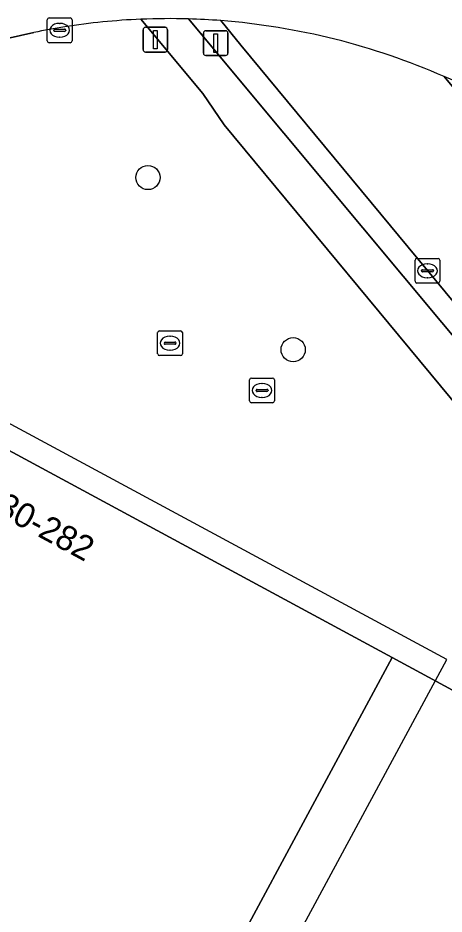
# Model space of a CAD drawing. Extents: x 159489 to 160304, y 383825 to 384531.
# Drawn here: x 159952.57 to 159969.79, y 384218.65 to 384254.88 of the extents above; entities that cross this region are included whole.
import ezdxf

# ---------------------------------------------------------------- set-up
doc = ezdxf.new("R2010")
doc.units = 0
for name, color, linetype in [('IMGEO_Berm_groen', 7, 'Continuous'), ('IMGEO_Boom', 7, 'Continuous'), ('IMGEO_Fietspad_gesloten', 7, 'Continuous'), ('IMGEO_Groenvoorziening', 7, 'Continuous'), ('IMGEO_Kolk', 7, 'Continuous'), ('IMGEO_Lichtmast', 7, 'Continuous'), ('IMGEO_OVBaan_gesloten', 7, 'Continuous'), ('IMGEO_Pand', 7, 'Continuous'), ('IMGEO_Pand_nummerreeks', 7, 'Continuous'), ('IMGEO_Pand_overbouw', 7, 'Continuous'), ('IMGEO_Rijbaan_lokaal_gesloten', 7, 'Continuous'), ('IMGEO_Verkeerseiland_open', 7, 'Continuous'), ('IMGEO_Verkeersregelinstallatiepaal', 7, 'Continuous'), ('IMGEO_Voetpad_open', 7, 'Continuous')]:
    doc.layers.add(name, color=color, linetype=linetype)

msp = doc.modelspace()

# ---------------------------------------------------------------- linework, layer by layer
at = {"layer": 'IMGEO_Berm_groen'}
msp.add_lwpolyline([(159969.786, 384252.506), (160028.141, 384182.05), (160030.552, 384184.07), (159981.084, 384243.71)], dxfattribs=at)
msp.add_arc((159961.544, 384231.122), 22.918, 46.5819, 68.9231, dxfattribs=at)
at = {"layer": 'IMGEO_Boom'}
for centre in [(159957.82, 384248.425), (159963.688, 384241.466)]:
    msp.add_circle(centre, 0.489, dxfattribs=at)
at = {"layer": 'IMGEO_Fietspad_gesloten'}
for points in [[(159957.532, 384254.825), (159960.033, 384251.817), (159960.897, 384250.561), (160029.527, 384167.731), (160030.452, 384166.645), (160032.238, 384164.549)], [(159961.686, 384252.179), (159959.937, 384254.261), (159959.452, 384254.838)], [(160032.453, 384167.34), (159961.686, 384252.179)]]:
    msp.add_lwpolyline(points, dxfattribs=at)
msp.add_arc((159958.681, 384226.911), 27.937, 88.4187, 92.3572, dxfattribs=at)
at = {"layer": 'IMGEO_Groenvoorziening'}
msp.add_lwpolyline([(159982.197, 384221.174), (159967.686, 384229.02), (159951.577, 384199.109), (159928.39, 384211.596), (159927.794, 384210.489), (159967.949, 384188.903), (159982.328, 384181.173), (159984.895, 384182.371), (159986.818, 384178.787), (159991.4, 384176.315), (159993.92, 384177.521), (159995.948, 384173.906), (160023.092, 384159.367), (160025.82, 384157.906), (160029.234, 384164.348)], close=True, dxfattribs=at)
at = {"layer": 'IMGEO_Kolk'}
for p, q in [((159953.753, 384253.951), (159953.753, 384254.803)), ((159953.828, 384254.877), (159954.68, 384254.877)), ((159954.754, 384254.803), (159954.754, 384253.951)), ((159954.055, 384254.42), (159954.453, 384254.42)), ((159954.241, 384254.657), (159954.266, 384254.657)), ((159954.012, 384254.371), (159954.012, 384254.383)), ((159954.45, 384254.334), (159954.052, 384254.334)), ((159954.264, 384254.097), (159954.239, 384254.097)), ((159954.496, 384254.383), (159954.496, 384254.371)), ((159954.68, 384253.877), (159953.828, 384253.877)), ((159968.614, 384244.23), (159968.614, 384245.082)), ((159968.689, 384245.156), (159969.541, 384245.156)), ((159969.615, 384245.082), (159969.615, 384244.23)), ((159968.873, 384244.65), (159968.873, 384244.662)), ((159969.311, 384244.613), (159968.913, 384244.613)), ((159968.916, 384244.699), (159969.314, 384244.699)), ((159969.102, 384244.936), (159969.127, 384244.936)), ((159969.357, 384244.662), (159969.357, 384244.65)), ((159969.125, 384244.376), (159969.1, 384244.376)), ((159969.541, 384244.156), (159968.689, 384244.156)), ((159958.212, 384241.304), (159958.212, 384242.156)), ((159958.287, 384242.23), (159959.139, 384242.23)), ((159959.213, 384242.156), (159959.213, 384241.304)), ((159958.471, 384241.724), (159958.471, 384241.736)), ((159958.514, 384241.773), (159958.912, 384241.773)), ((159958.7, 384242.01), (159958.725, 384242.01)), ((159958.955, 384241.736), (159958.955, 384241.724)), ((159958.909, 384241.687), (159958.511, 384241.687)), ((159958.723, 384241.45), (159958.698, 384241.45)), ((159959.139, 384241.23), (159958.287, 384241.23)), ((159962.004, 384240.319), (159962.856, 384240.319)), ((159961.929, 384239.393), (159961.929, 384240.245)), ((159962.417, 384240.099), (159962.442, 384240.099)), ((159962.93, 384240.245), (159962.93, 384239.393)), ((159962.188, 384239.813), (159962.188, 384239.825)), ((159962.626, 384239.776), (159962.228, 384239.776)), ((159962.231, 384239.862), (159962.629, 384239.862)), ((159962.672, 384239.825), (159962.672, 384239.813)), ((159962.856, 384239.319), (159962.004, 384239.319)), ((159962.44, 384239.539), (159962.415, 384239.539))]:
    msp.add_line(p, q, dxfattribs=at)
for points in [[(159953.753, 384253.951), (159953.753, 384254.803)], [(159953.828, 384254.877), (159954.68, 384254.877)], [(159954.754, 384254.803), (159954.754, 384253.951)], [(159954.68, 384253.877), (159953.828, 384253.877)], [(159968.614, 384244.23), (159968.614, 384245.082)], [(159968.689, 384245.156), (159969.541, 384245.156)], [(159969.615, 384245.082), (159969.615, 384244.23)], [(159969.541, 384244.156), (159968.689, 384244.156)], [(159958.212, 384241.304), (159958.212, 384242.156)], [(159958.287, 384242.23), (159959.139, 384242.23)], [(159959.213, 384242.156), (159959.213, 384241.304)], [(159959.139, 384241.23), (159958.287, 384241.23)], [(159962.004, 384240.319), (159962.856, 384240.319)], [(159961.929, 384239.393), (159961.929, 384240.245)], [(159962.93, 384240.245), (159962.93, 384239.393)], [(159962.856, 384239.319), (159962.004, 384239.319)]]:
    msp.add_lwpolyline(points, dxfattribs=at)
for centre, radius, start, end in [((159953.83, 384254.801), 0.0765, 91.552, 178.448), ((159953.83, 384254.801), 0.0765, 91.552, 178.448), ((159954.678, 384254.801), 0.0765, 1.552, 88.448), ((159954.678, 384254.801), 0.0765, 1.552, 88.448), ((159954.052, 384254.38), 0.0403, 85.8775, 175.7526), ((159954.457, 384254.382), 0.0386, 1.7309, 96.639), ((159954.049, 384254.37), 0.0366, 178.938, 274.7102), ((159954.453, 384254.377), 0.043, 264.8664, 352.4533), ((159953.83, 384253.953), 0.0765, 181.552, 268.448), ((159953.83, 384253.953), 0.0765, 181.552, 268.448), ((159954.678, 384253.953), 0.0765, 271.552, 358.448), ((159954.678, 384253.953), 0.0765, 271.552, 358.448), ((159968.691, 384245.08), 0.0765, 91.552, 178.448), ((159968.691, 384245.08), 0.0765, 91.552, 178.448), ((159969.539, 384245.08), 0.0765, 1.552, 88.448), ((159969.539, 384245.08), 0.0765, 1.552, 88.448), ((159968.913, 384244.659), 0.0403, 85.8775, 175.7526), ((159968.91, 384244.649), 0.0366, 178.938, 274.7102), ((159969.314, 384244.656), 0.043, 264.8664, 352.4533), ((159969.318, 384244.661), 0.0386, 1.7309, 96.639), ((159968.691, 384244.232), 0.0765, 181.552, 268.448), ((159968.691, 384244.232), 0.0765, 181.552, 268.448), ((159969.539, 384244.232), 0.0765, 271.552, 358.448), ((159969.539, 384244.232), 0.0765, 271.552, 358.448), ((159958.289, 384242.154), 0.0765, 91.552, 178.448), ((159958.289, 384242.154), 0.0765, 91.552, 178.448), ((159959.137, 384242.154), 0.0765, 1.552, 88.448), ((159959.137, 384242.154), 0.0765, 1.552, 88.448), ((159958.511, 384241.733), 0.0403, 85.8775, 175.7526), ((159958.508, 384241.723), 0.0366, 178.938, 274.7102), ((159958.912, 384241.73), 0.043, 264.8664, 352.4533), ((159958.916, 384241.735), 0.0386, 1.7309, 96.639), ((159958.289, 384241.306), 0.0765, 181.552, 268.448), ((159958.289, 384241.306), 0.0765, 181.552, 268.448), ((159959.137, 384241.306), 0.0765, 271.552, 358.448), ((159959.137, 384241.306), 0.0765, 271.552, 358.448), ((159962.006, 384240.243), 0.0765, 91.552, 178.448), ((159962.006, 384240.243), 0.0765, 91.552, 178.448), ((159962.854, 384240.243), 0.0765, 1.552, 88.448), ((159962.854, 384240.243), 0.0765, 1.552, 88.448), ((159962.228, 384239.822), 0.0403, 85.8775, 175.7526), ((159962.225, 384239.812), 0.0366, 178.938, 274.7102), ((159962.629, 384239.819), 0.043, 264.8664, 352.4533), ((159962.633, 384239.824), 0.0386, 1.7309, 96.639), ((159962.006, 384239.395), 0.0765, 181.552, 268.448), ((159962.006, 384239.395), 0.0765, 181.552, 268.448), ((159962.854, 384239.395), 0.0765, 271.552, 358.448), ((159962.854, 384239.395), 0.0765, 271.552, 358.448)]:
    msp.add_arc(centre, radius, start, end, dxfattribs=at)
for centre, major_axis, ratio, start_param, end_param in [((159954.24, 384254.377), (-0.387, 0.002), 0.722429, 4.712389, 7.853982), ((159954.265, 384254.377), (-0.39, 0.002), 0.717154, 1.570796, 4.712389), ((159969.101, 384244.656), (-0.387, 0.002), 0.722429, 4.712389, 7.853982), ((159969.126, 384244.656), (-0.39, 0.002), 0.717154, 1.570796, 4.712389), ((159958.699, 384241.73), (-0.387, 0.002), 0.722429, 4.712389, 7.853982), ((159958.724, 384241.73), (-0.39, 0.002), 0.717154, 1.570796, 4.712389), ((159962.416, 384239.819), (-0.387, 0.002), 0.722429, 4.712389, 7.853982), ((159962.441, 384239.819), (-0.39, 0.002), 0.717154, 1.570796, 4.712389)]:
    msp.add_ellipse(centre, major_axis=major_axis, ratio=ratio, start_param=start_param, end_param=end_param, dxfattribs=at)
at = {"layer": 'IMGEO_Lichtmast'}
for p, q in [((159960.063, 384253.458), (159960.063, 384254.258)), ((159960.063, 384254.258), (159960.063, 384253.458)), ((159960.163, 384254.358), (159960.953, 384254.358)), ((159960.953, 384254.358), (159960.163, 384254.358)), ((159961.053, 384254.258), (159961.053, 384253.458)), ((159961.053, 384253.458), (159961.053, 384254.258)), ((159960.953, 384253.358), (159960.163, 384253.358)), ((159960.163, 384253.358), (159960.953, 384253.358))]:
    msp.add_line(p, q, dxfattribs=at)
msp.add_lwpolyline([(159960.483, 384254.233), (159960.633, 384254.233), (159960.633, 384253.483), (159960.483, 384253.483), (159960.483, 384254.233)], dxfattribs=at)
for centre, start, end in [((159960.163, 384254.258), 90, 180), ((159960.163, 384254.258), 90, 180), ((159960.953, 384254.258), 0, 90), ((159960.953, 384254.258), 360, 90), ((159960.163, 384253.458), 180, 270), ((159960.163, 384253.458), 180, 270), ((159960.953, 384253.458), 270, 0), ((159960.953, 384253.458), 270, 0)]:
    msp.add_arc(centre, 0.1, start, end, dxfattribs=at)
at = {"layer": 'IMGEO_OVBaan_gesloten'}
msp.add_lwpolyline([(159951.164, 384253.832), (159953.211, 384254.289)], dxfattribs=at)
for centre, radius, start, end in [((159958.697, 384227.713), 27.137, 92.4615, 98.9856), ((159958.681, 384226.911), 27.937, 88.4187, 92.3572), ((159958.68, 384228.095), 26.754, 85.5364, 88.3462), ((159958.606, 384227.036), 27.816, 66.3012, 85.5546), ((159958.952, 384226.397), 28.477, 99.0769, 101.6297), ((159961.544, 384231.122), 22.918, 46.5819, 68.9231)]:
    msp.add_arc(centre, radius, start, end, dxfattribs=at)
at = {"layer": 'IMGEO_Pand'}
msp.add_lwpolyline([(159967.686, 384229.02), (159944.524, 384241.543), (159928.39, 384211.596), (159951.577, 384199.109)], close=True, dxfattribs=at)
at = {"layer": 'IMGEO_Pand_overbouw'}
msp.add_lwpolyline([(159953.299, 384198.181), (159969.896, 384228.943), (159943.238, 384243.325), (159926.605, 384212.558), (159928.39, 384211.596), (159944.07, 384240.7), (159944.524, 384241.543), (159945.039, 384241.265), (159967.686, 384229.02), (159951.577, 384199.109)], close=True, dxfattribs=at)
at = {"layer": 'IMGEO_Rijbaan_lokaal_gesloten'}
for points in [[(159960.762, 384254.768), (159961.57, 384253.773), (160030.037, 384171.103), (160034.331, 384174.603), (160033.026, 384176.155), (160028.141, 384182.05)], [(160028.141, 384182.05), (159969.786, 384252.506)]]:
    msp.add_lwpolyline(points, dxfattribs=at)
msp.add_arc((159958.606, 384227.036), 27.816, 66.3012, 85.5546, dxfattribs=at)
at = {"layer": 'IMGEO_Verkeerseiland_open'}
for points in [[(159959.452, 384254.838), (159959.937, 384254.261), (159961.686, 384252.179), (160032.453, 384167.34)], [(159961.57, 384253.773), (159960.762, 384254.768)], [(160031.533, 384169.297), (160030.037, 384171.103), (159961.57, 384253.773)]]:
    msp.add_lwpolyline(points, dxfattribs=at)
msp.add_arc((159958.68, 384228.095), 26.754, 85.5364, 88.3462, dxfattribs=at)
at = {"layer": 'IMGEO_Verkeersregelinstallatiepaal'}
for p, q in [((159957.62, 384253.598), (159957.62, 384254.398)), ((159957.62, 384254.398), (159957.62, 384253.598)), ((159957.72, 384254.498), (159958.51, 384254.498)), ((159958.51, 384254.498), (159957.72, 384254.498)), ((159958.61, 384254.398), (159958.61, 384253.598)), ((159958.61, 384253.598), (159958.61, 384254.398)), ((159958.51, 384253.498), (159957.72, 384253.498)), ((159957.72, 384253.498), (159958.51, 384253.498))]:
    msp.add_line(p, q, dxfattribs=at)
msp.add_lwpolyline([(159958.04, 384254.373), (159958.19, 384254.373), (159958.19, 384253.623), (159958.04, 384253.623), (159958.04, 384254.373)], dxfattribs=at)
for centre, start, end in [((159957.72, 384254.398), 90, 180), ((159957.72, 384254.398), 90, 180), ((159958.51, 384254.398), 0, 90), ((159958.51, 384254.398), 360, 90), ((159957.72, 384253.598), 180, 270), ((159957.72, 384253.598), 180, 270), ((159958.51, 384253.598), 270, 0), ((159958.51, 384253.598), 270, 0)]:
    msp.add_arc(centre, 0.1, start, end, dxfattribs=at)
at = {"layer": 'IMGEO_Voetpad_open'}
for points in [[(159960.897, 384250.561), (159960.033, 384251.817), (159957.532, 384254.825)], [(159953.211, 384254.289), (159951.164, 384253.832)], [(159938.258, 384245.722), (159936.217, 384243.18), (159934.691, 384241.032), (159937.261, 384239.696), (159936.314, 384237.873), (159922.992, 384213.07), (159925.664, 384211.634), (159927.794, 384210.489), (159928.39, 384211.596), (159944.524, 384241.543), (159967.686, 384229.02), (159982.197, 384221.174), (160029.234, 384164.348), (160030.452, 384166.645), (160029.527, 384167.731), (159960.897, 384250.561)]]:
    msp.add_lwpolyline(points, dxfattribs=at)
for centre, radius, start, end in [((159958.697, 384227.713), 27.137, 92.4615, 98.9856), ((159958.952, 384226.397), 28.477, 99.0769, 101.6297)]:
    msp.add_arc(centre, radius, start, end, dxfattribs=at)

# ---------------------------------------------------------------- texts
at = {"layer": 'IMGEO_Pand_nummerreeks'}
msp.add_text('30-282', height=1, rotation=331.5985, dxfattribs=at).set_placement((159951.624, 384234.863))

doc.saveas('drawing.dxf')
